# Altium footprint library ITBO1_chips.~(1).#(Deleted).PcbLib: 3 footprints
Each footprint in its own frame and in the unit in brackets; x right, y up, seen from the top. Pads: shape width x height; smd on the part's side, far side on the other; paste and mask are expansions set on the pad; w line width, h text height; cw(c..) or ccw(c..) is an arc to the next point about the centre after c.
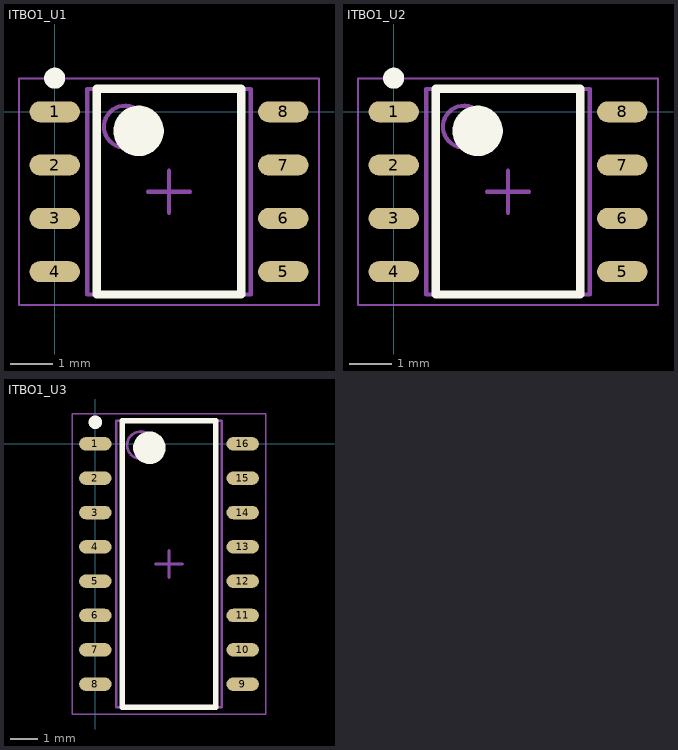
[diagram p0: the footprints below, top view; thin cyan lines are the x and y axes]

## ITBO1_U1 [mm] "TSOP, 8-Leads, Body 4.85x3.85mm, Pitch 1.27mm, IPC Medium Density"
height 1.25
pads (8):
  oval 1.2x0.5 smd: 1(0,0) 2(0,-1.27) 3(0,-2.54) 4(0,-3.81) 5(5.45,-3.81) 6(5.45,-2.54) 7(5.45,-1.27) 8(5.45,0)
Top Overlay:
  circle w0.25: c0,0.8 r0.125
  circle w0.6: c2,-0.455 r0.3
  lines w0.2: 1,-4.355 1,0.545 4.45,0.545 4.45,-4.355 1,-4.355
Mechanical 13:
  circle w0.1: c1.675,-0.355 r0.5
  lines w0.1: 0.775,-4.355 0.775,0.545 4.675,0.545 4.675,-4.355 0.775,-4.355
Mechanical 15:
  lines w0.05: -0.85,-4.605 -0.85,0.795 6.3,0.795 6.3,-4.605 -0.85,-4.605
  lines w0.1: 2.225,-1.905 3.225,-1.905 ; 2.725,-2.405 2.725,-1.405
3D body "ITBO1_U2.step": height 1.25, standoff 0, extent -0.2,-4.355 5.65,0.545

## ITBO1_U2 [mm] "TSOP, 8-Leads, Body 4.85x3.85mm, Pitch 1.27mm, IPC Medium Density"
height 1.25
pads (8):
  oval 1.2x0.5 smd: 1(0,0) 2(0,-1.27) 3(0,-2.54) 4(0,-3.81) 5(5.45,-3.81) 6(5.45,-2.54) 7(5.45,-1.27) 8(5.45,0)
Top Overlay:
  circle w0.6: c2,-0.455 r0.3
  circle w0.25: c0,0.8 r0.125
  lines w0.2: 1,-4.355 4.45,-4.355 4.45,0.545 1,0.545 1,-4.355
Mechanical 13:
  circle w0.1: c1.675,-0.355 r0.5
  lines w0.1: 0.775,-4.355 4.675,-4.355 4.675,0.545 0.775,0.545 0.775,-4.355
Mechanical 15:
  lines w0.05: -0.85,-4.605 6.3,-4.605 6.3,0.795 -0.85,0.795 -0.85,-4.605
  lines w0.1: 2.225,-1.905 3.225,-1.905 ; 2.725,-2.405 2.725,-1.405
3D body "ITBO1_U2.step": height 1.25, standoff 0, extent -0.2,-4.355 5.65,0.545

## ITBO1_U3 [mm]
height 1.25
pads (16):
  oval 1.2x0.5 smd: 1(0,0) 2(0,-1.27) 3(0,-2.54) 4(0,-3.81) 5(0,-5.08) 6(0,-6.35) 7(0,-7.62) 8(0,-8.89) 9(5.45,-8.89) 10(5.45,-7.62) 11(5.45,-6.35) 12(5.45,-5.08) 13(5.45,-3.81) 14(5.45,-2.54) 15(5.45,-1.27) 16(5.45,0)
Top Overlay:
  circle w0.25: c0,0.8 r0.125
  circle w0.6: c2,-0.145 r0.3
  lines w0.2: 1,-9.745 1,0.855 4.45,0.855 4.45,-9.745 1,-9.745
Mechanical 13:
  circle w0.1: c1.675,-0.045 r0.5
  lines w0.1: 0.775,-9.745 0.775,0.855 4.675,0.855 4.675,-9.745 0.775,-9.745
Mechanical 15:
  lines w0.05: -0.85,-9.995 -0.85,1.105 6.3,1.105 6.3,-9.995 -0.85,-9.995
  lines w0.1: 2.225,-4.445 3.225,-4.445 ; 2.725,-4.945 2.725,-3.945
3D body "SOP127P600-8N.step": height 1.25, standoff 0, extent -0.2,-9.745 5.65,0.855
